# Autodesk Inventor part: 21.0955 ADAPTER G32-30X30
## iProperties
Created: 2012-10
Part Number: 21.0955 ADAPTER G32-30X30
Document SubType Name: Modeling
Designer: Administrator
Density: 2.71 g/cm^3
Material: Aluminum-6061
Mass: 9.65328 g
Surface Area: 29.5311 cm^2
Volume: 3.56209 cm^3
Author: Administrator
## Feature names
1. Base1
